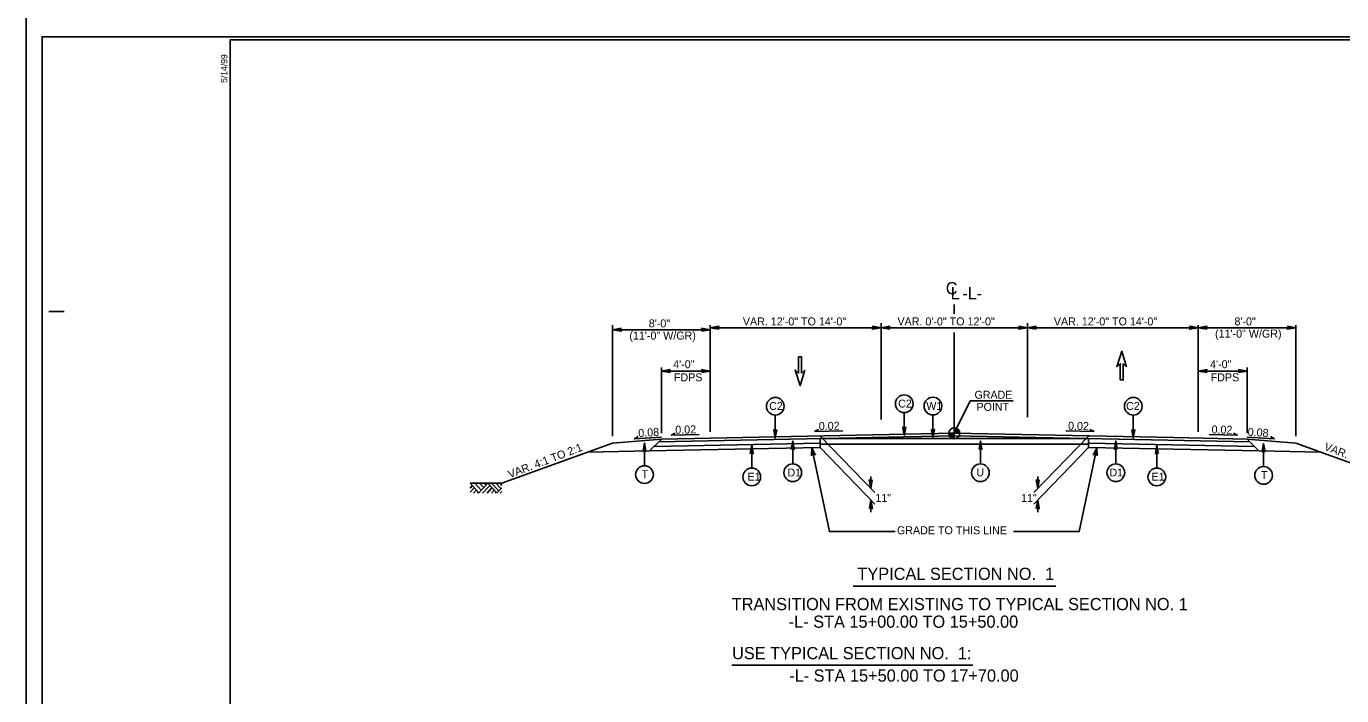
# Model space of a CAD drawing. Extents: x 1901670 to 1902225, y 193498 to 194278.
# Drawn here: x 1901965.8 to 1902073.7, y 194101.8 to 194156.6 of the extents above; entities that cross this region are included whole.
import ezdxf

# ---------------------------------------------------------------- set-up
doc = ezdxf.new("R2010")
doc.units = 0
for name, color, linetype in [('Old_Level_1', 7, 'Continuous'), ('Old_Level_11', 7, 'Continuous'), ('Old_Level_2', 7, 'Continuous'), ('Old_Level_20', 7, 'Continuous'), ('Prop Dimension', 7, 'Continuous'), ('Prop Dimension Text', 7, 'Continuous'), ('Sheet Border Standard 30in CELL', 7, 'Continuous'), ('Sheet Cutting Line CELL', 7, 'Continuous'), ('Sheet Plot Border Inside CELL', 7, 'Continuous'), ('Sheet Plot Border Outside CELL', 7, 'Continuous'), ('Typical Pavement Slope CELL', 7, 'Continuous'), ('Typical Terminator CELL', 7, 'Continuous'), ('Typical Text Grade Point CELL', 7, 'Continuous')]:
    doc.layers.add(name, color=color, linetype=linetype)

# ---------------------------------------------------------------- blocks, each defined once
blk = doc.blocks.new('TERMINATOR')
at = {"layer": 'Typical Terminator CELL'}
blk.add_lwpolyline([(-0.469, 0.081), (0, 0), (-0.471, -0.083), (-0.411, 0)], close=True, dxfattribs=at)

msp = doc.modelspace()

# ---------------------------------------------------------------- linework, layer by layer
at = {"layer": 'Old_Level_1'}
for p, q in [((1902041.9, 194133.06), (1902041.9, 194133.82)), ((1902041.9, 194123.27), (1902041.9, 194131.54)), ((1902041.9, 194123.27), (1902017.9, 194122.79)), ((1902018.69, 194123.11), (1902019.02, 194123.27)), ((1902021, 194123.16), (1902018.69, 194123.11)), ((1902030.45, 194123.41), (1902030.78, 194123.58)), ((1902032.76, 194123.46), (1902030.45, 194123.41)), ((1902041.45, 194123.27), (1902041.9, 194123.27)), ((1902041.9, 194123.27), (1902041.9, 194123.72)), ((1902042.35, 194123.27), (1902041.9, 194123.27)), ((1902041.9, 194122.82), (1902041.9, 194123.27)), ((1902041.9, 194123.27), (1902041.9, 194122.82)), ((1902041.9, 194123.27), (1902059.9, 194122.91)), ((1902051.04, 194123.46), (1902053.35, 194123.41)), ((1902053.35, 194123.41), (1902053.02, 194123.58)), ((1902062.8, 194123.16), (1902065.11, 194123.11)), ((1902065.11, 194123.11), (1902064.78, 194123.27)), ((1902017.9, 194122.79), (1902013.9, 194122.45)), ((1902015.67, 194122.82), (1902015.99, 194123)), ((1902017.91, 194122.96), (1902015.67, 194122.82)), ((1902016.93, 194121.82), (1902017.9, 194122.79)), ((1902030.9, 194122.1), (1902016.93, 194121.82)), ((1902030.9, 194122.46), (1902017.31, 194122.19)), ((1902041.9, 194123.05), (1902017.68, 194122.56)), ((1902030.9, 194123.03), (1902035.38, 194118.41)), ((1902030.9, 194122.83), (1902030.9, 194122.1)), ((1902052.9, 194122.83), (1902030.9, 194122.83)), ((1902030.9, 194122.38), (1902052.9, 194122.38)), ((1902030.9, 194122.1), (1902035.38, 194117.47)), ((1902041.9, 194123.05), (1902066.12, 194122.56)), ((1902052.9, 194123.03), (1902048.42, 194118.41)), ((1902052.9, 194122.1), (1902048.42, 194117.47)), ((1902052.9, 194122.83), (1902052.9, 194122.1)), ((1902052.9, 194122.46), (1902066.5, 194122.19)), ((1902052.9, 194122.1), (1902066.87, 194121.82)), ((1902059.9, 194122.91), (1902065.9, 194122.79)), ((1902065.9, 194122.96), (1902068.13, 194122.82)), ((1902066.87, 194121.82), (1902065.9, 194122.79)), ((1902065.9, 194122.79), (1902069.9, 194122.45)), ((1902068.13, 194122.82), (1902067.81, 194123)), ((1902016.93, 194121.82), (1902011.86, 194121.72)), ((1902066.87, 194121.82), (1902071.94, 194121.72)), ((1902002.21, 194119.17), (1902002.93, 194118.39)), ((1902002.21, 194118.77), (1902002.39, 194118.97)), ((1902002.21, 194118.43), (1902002.55, 194118.8)), ((1902002.6, 194119.18), (1902003.13, 194118.6)), ((1902002.93, 194118.39), (1902003.66, 194119.18)), ((1902003, 194119.18), (1902003.33, 194118.82)), ((1902003.24, 194118.37), (1902003.83, 194119)), ((1902003.4, 194119.18), (1902003.53, 194119.03)), ((1902003.61, 194118.37), (1902004.01, 194118.8)), ((1902003.66, 194119.18), (1902004.4, 194118.38)), ((1902003.98, 194119.18), (1902004.56, 194118.55)), ((1902004.32, 194119.18), (1902004.73, 194118.73)), ((1902004.4, 194118.38), (1902004.81, 194118.81)), ((1902004.64, 194119.18), (1902004.81, 194118.99)), ((1902035.06, 194119.74), (1902035.06, 194118.74)), ((1902048.74, 194119.74), (1902048.74, 194118.74)), ((1902002.5, 194118.37), (1902002.72, 194118.61)), ((1902002.81, 194118.37), (1902002.88, 194118.45)), ((1902003.98, 194118.37), (1902004.19, 194118.6)), ((1902004.27, 194118.37), (1902004.34, 194118.45)), ((1902004.67, 194118.37), (1902004.81, 194118.51)), ((1902035.06, 194117.8), (1902035.06, 194116.8)), ((1902048.74, 194117.8), (1902048.74, 194116.8))]:
    msp.add_line(p, q, dxfattribs=at)
for points in [[(1902041.45, 194123.27), (1902041.45, 194123.22)], [(1902041.46, 194123.27), (1902041.46, 194123.16)], [(1902041.47, 194123.27), (1902041.47, 194123.13)], [(1902041.48, 194123.27), (1902041.48, 194123.1)], [(1902041.49, 194123.27), (1902041.49, 194123.08)], [(1902041.5, 194123.27), (1902041.5, 194123.06)], [(1902041.51, 194123.27), (1902041.51, 194123.05)], [(1902041.52, 194123.27), (1902041.52, 194123.03)], [(1902041.52, 194123.27), (1902041.52, 194123.02)], [(1902041.53, 194123.27), (1902041.53, 194123)], [(1902041.54, 194123.27), (1902041.54, 194122.99)], [(1902041.55, 194123.27), (1902041.55, 194122.98)], [(1902041.56, 194123.27), (1902041.56, 194122.97)], [(1902041.57, 194123.27), (1902041.57, 194122.96)], [(1902041.58, 194123.27), (1902041.58, 194122.95)], [(1902041.59, 194123.27), (1902041.59, 194122.94)], [(1902041.6, 194123.27), (1902041.6, 194122.93)], [(1902041.61, 194123.27), (1902041.61, 194122.93)], [(1902041.61, 194123.27), (1902041.61, 194122.92)], [(1902041.62, 194123.27), (1902041.62, 194122.91)], [(1902041.63, 194123.27), (1902041.63, 194122.9)], [(1902041.64, 194123.27), (1902041.64, 194122.9)], [(1902041.65, 194123.27), (1902041.65, 194122.89)], [(1902041.66, 194123.27), (1902041.66, 194122.89)], [(1902041.67, 194123.27), (1902041.67, 194122.88)], [(1902041.68, 194123.27), (1902041.68, 194122.87)], [(1902041.69, 194123.27), (1902041.69, 194122.87)], [(1902041.7, 194123.27), (1902041.7, 194122.86)], [(1902041.7, 194123.27), (1902041.7, 194122.86)], [(1902041.71, 194123.27), (1902041.71, 194122.86)], [(1902041.72, 194123.27), (1902041.72, 194122.85)], [(1902041.73, 194123.27), (1902041.73, 194122.85)], [(1902041.74, 194123.27), (1902041.74, 194122.84)], [(1902041.75, 194123.27), (1902041.75, 194122.84)], [(1902041.76, 194123.27), (1902041.76, 194122.84)], [(1902041.77, 194123.27), (1902041.77, 194122.84)], [(1902041.78, 194123.27), (1902041.78, 194122.83)], [(1902041.79, 194123.27), (1902041.79, 194122.83)], [(1902041.79, 194123.27), (1902041.79, 194122.83)], [(1902041.8, 194123.27), (1902041.8, 194122.83)], [(1902041.81, 194123.27), (1902041.81, 194122.82)], [(1902041.82, 194123.27), (1902041.82, 194122.82)], [(1902041.83, 194123.27), (1902041.83, 194122.82)], [(1902041.84, 194123.27), (1902041.84, 194122.82)], [(1902041.85, 194123.27), (1902041.85, 194122.82)], [(1902041.86, 194123.27), (1902041.86, 194122.82)], [(1902041.87, 194123.27), (1902041.87, 194122.82)], [(1902041.88, 194123.27), (1902041.88, 194122.82)], [(1902041.88, 194123.27), (1902041.88, 194122.82)], [(1902041.89, 194123.27), (1902041.89, 194122.82), (1902041.89, 194122.82)], [(1902041.9, 194123.72), (1902041.9, 194123.72), (1902041.9, 194123.27)], [(1902041.91, 194123.72), (1902041.91, 194123.27)], [(1902041.92, 194123.71), (1902041.92, 194123.27)], [(1902041.93, 194123.71), (1902041.93, 194123.27)], [(1902041.94, 194123.71), (1902041.94, 194123.27)], [(1902041.95, 194123.71), (1902041.95, 194123.27)], [(1902041.96, 194123.71), (1902041.96, 194123.27)], [(1902041.97, 194123.71), (1902041.97, 194123.27)], [(1902041.98, 194123.71), (1902041.98, 194123.27)], [(1902041.99, 194123.71), (1902041.99, 194123.27)], [(1902041.99, 194123.71), (1902041.99, 194123.27)], [(1902042, 194123.7), (1902042, 194123.27)], [(1902042.01, 194123.7), (1902042.01, 194123.27)], [(1902042.02, 194123.7), (1902042.02, 194123.27)], [(1902042.03, 194123.7), (1902042.03, 194123.27)], [(1902042.04, 194123.69), (1902042.04, 194123.27)], [(1902042.05, 194123.69), (1902042.05, 194123.27)], [(1902042.06, 194123.69), (1902042.06, 194123.27)], [(1902042.07, 194123.68), (1902042.07, 194123.27)], [(1902042.08, 194123.68), (1902042.08, 194123.27)], [(1902042.08, 194123.68), (1902042.08, 194123.27)], [(1902042.09, 194123.67), (1902042.09, 194123.27)], [(1902042.1, 194123.67), (1902042.1, 194123.27)], [(1902042.11, 194123.66), (1902042.11, 194123.27)], [(1902042.12, 194123.66), (1902042.12, 194123.27)], [(1902042.13, 194123.65), (1902042.13, 194123.27)], [(1902042.14, 194123.65), (1902042.14, 194123.27)], [(1902042.15, 194123.64), (1902042.15, 194123.27)], [(1902042.16, 194123.64), (1902042.16, 194123.27)], [(1902042.17, 194123.63), (1902042.17, 194123.27)], [(1902042.17, 194123.62), (1902042.17, 194123.27)], [(1902042.18, 194123.62), (1902042.18, 194123.27)], [(1902042.19, 194123.61), (1902042.19, 194123.27)], [(1902042.2, 194123.6), (1902042.2, 194123.27)], [(1902042.21, 194123.59), (1902042.21, 194123.27)], [(1902042.22, 194123.58), (1902042.22, 194123.27)], [(1902042.23, 194123.57), (1902042.23, 194123.27)], [(1902042.24, 194123.56), (1902042.24, 194123.27)], [(1902042.25, 194123.55), (1902042.25, 194123.27)], [(1902042.26, 194123.54), (1902042.26, 194123.27)], [(1902042.26, 194123.53), (1902042.26, 194123.27)], [(1902042.27, 194123.52), (1902042.27, 194123.27)], [(1902042.28, 194123.5), (1902042.28, 194123.27)], [(1902042.29, 194123.49), (1902042.29, 194123.27)], [(1902042.3, 194123.47), (1902042.3, 194123.27)], [(1902042.31, 194123.45), (1902042.31, 194123.27)], [(1902042.32, 194123.43), (1902042.32, 194123.27)], [(1902042.33, 194123.41), (1902042.33, 194123.27)], [(1902042.34, 194123.38), (1902042.34, 194123.27)], [(1902042.35, 194123.33), (1902042.35, 194123.27)], [(1902030.52, 194121.48), (1902030.22, 194122.08), (1902030.19, 194121.41)], [(1902030.22, 194122.08), (1902031.66, 194115.23), (1902037.05, 194115.23)], [(1902053.58, 194122.08), (1902052.14, 194115.23), (1902046.75, 194115.23)], [(1902053.28, 194121.48), (1902053.58, 194122.08), (1902053.61, 194121.41)], [(1902002.21, 194119.18), (1902004.81, 194119.18)]]:
    msp.add_lwpolyline(points, dxfattribs=at)
msp.add_circle((1902041.9, 194123.27), 0.45, dxfattribs=at)
for start, end in [(179.9905, 269.9905), (359.9905, 89.9905)]:
    msp.add_arc((1902041.9, 194123.27), 0.45, start, end, dxfattribs=at)
at = {"layer": 'Old_Level_11'}
for p, q in [((1902027.23, 194124.76), (1902027.23, 194122.89)), ((1902037.8, 194124.96), (1902037.8, 194123.09)), ((1902040.15, 194124.77), (1902040.15, 194122.9)), ((1902056.57, 194124.76), (1902056.57, 194122.89)), ((1902016.51, 194120.6), (1902016.51, 194122.48)), ((1902025.3, 194120.42), (1902025.3, 194122.29)), ((1902028.66, 194120.76), (1902028.66, 194122.64)), ((1902044.04, 194120.76), (1902044.04, 194122.64)), ((1902055.14, 194120.76), (1902055.14, 194122.64)), ((1902058.5, 194120.42), (1902058.5, 194122.29)), ((1902067.25, 194120.55), (1902067.25, 194122.42)), ((1902033.61, 194110.75), (1902050.23, 194110.75)), ((1902023.67, 194104.25), (1902043.41, 194104.25))]:
    msp.add_line(p, q, dxfattribs=at)
for points in [[(1902027.35, 194123.56), (1902027.23, 194122.89), (1902027.12, 194123.56), (1902027.23, 194123.47)], [(1902037.92, 194123.76), (1902037.8, 194123.09), (1902037.68, 194123.76), (1902037.8, 194123.68)], [(1902040.03, 194123.57), (1902040.15, 194122.9), (1902040.27, 194123.58), (1902040.15, 194123.49)], [(1902056.45, 194123.56), (1902056.57, 194122.89), (1902056.69, 194123.56), (1902056.57, 194123.47)], [(1902016.4, 194121.81), (1902016.51, 194122.48), (1902016.63, 194121.8), (1902016.51, 194121.89)], [(1902025.18, 194121.62), (1902025.3, 194122.29), (1902025.42, 194121.61), (1902025.3, 194121.7)], [(1902028.54, 194121.97), (1902028.66, 194122.64), (1902028.78, 194121.96), (1902028.66, 194122.05)], [(1902043.93, 194121.96), (1902044.04, 194122.64), (1902044.16, 194121.96), (1902044.04, 194122.05)], [(1902055.26, 194121.97), (1902055.14, 194122.64), (1902055.02, 194121.96), (1902055.14, 194122.05)], [(1902058.62, 194121.62), (1902058.5, 194122.29), (1902058.38, 194121.61), (1902058.5, 194121.7)], [(1902067.37, 194121.75), (1902067.25, 194122.42), (1902067.13, 194121.75), (1902067.25, 194121.83)]]:
    msp.add_lwpolyline(points, close=True, dxfattribs=at)
for centre in [(1902037.8, 194125.69), (1902027.23, 194125.48), (1902040.15, 194125.5), (1902056.57, 194125.48), (1902016.51, 194119.88), (1902025.3, 194119.69), (1902028.66, 194120.04), (1902044.04, 194120.04), (1902055.14, 194120.04), (1902058.5, 194119.69), (1902067.25, 194119.82)]:
    msp.add_circle(centre, 0.725, dxfattribs=at)
at = {"layer": 'Prop Dimension'}
for p, q in [((1902021.9, 194124.43), (1902021.9, 194132.13)), ((1902021.9, 194131.92), (1902035.9, 194131.92)), ((1902035.9, 194124.4), (1902035.9, 194132.29)), ((1902035.9, 194131.92), (1902047.9, 194131.92)), ((1902047.9, 194124.59), (1902047.9, 194132.29)), ((1902047.9, 194131.92), (1902061.9, 194131.92)), ((1902061.9, 194124.43), (1902061.9, 194132.13))]:
    msp.add_line(p, q, dxfattribs=at)
for points in [[(1902056.02, 194128.72), (1902055.75, 194128.97), (1902055.75, 194127.64), (1902055.5, 194127.64), (1902055.5, 194128.97), (1902055.23, 194128.72), (1902055.63, 194130)], [(1902056.02, 194128.72), (1902055.75, 194128.97), (1902055.75, 194127.64), (1902055.5, 194127.64), (1902055.5, 194128.97), (1902055.23, 194128.72), (1902055.63, 194130)], [(1902029.66, 194128.45), (1902029.39, 194128.2), (1902029.39, 194129.53), (1902029.14, 194129.53), (1902029.14, 194128.2), (1902028.87, 194128.45), (1902029.27, 194127.18)], [(1902029.66, 194128.45), (1902029.39, 194128.2), (1902029.39, 194129.53), (1902029.14, 194129.53), (1902029.14, 194128.2), (1902028.87, 194128.45), (1902029.27, 194127.18)]]:
    msp.add_lwpolyline(points, close=True, dxfattribs=at)
at = {"layer": 'Prop Dimension Text'}
for p, q in [((1902013.9, 194123.27), (1902013.9, 194132.13)), ((1902013.9, 194123.03), (1902013.9, 194132.13)), ((1902013.9, 194131.76), (1902021.9, 194131.76)), ((1902021.9, 194123.38), (1902021.9, 194132.13)), ((1902061.9, 194123.38), (1902061.9, 194132.13)), ((1902069.9, 194131.92), (1902061.9, 194131.92)), ((1902069.9, 194123.27), (1902069.9, 194132.13)), ((1902069.9, 194123.03), (1902069.9, 194132.13)), ((1902017.9, 194123.29), (1902017.9, 194128.65)), ((1902065.9, 194123.29), (1902065.9, 194128.65)), ((1902021.9, 194128.37), (1902017.9, 194128.37)), ((1902061.9, 194128.37), (1902065.9, 194128.37))]:
    msp.add_line(p, q, dxfattribs=at)
at = {"layer": 'Sheet Border Standard 30in CELL'}
for p, q in [((1901982.64, 194155.51), (1901982.64, 194155.51)), ((1901967.69, 194133.26), (1901968.94, 194133.26))]:
    msp.add_line(p, q, dxfattribs=at)
msp.add_lwpolyline([(1902132.54, 194155.51), (1901982.54, 194155.51), (1901982.54, 194050.51), (1902132.54, 194050.51)], close=True, dxfattribs=at)
at = {"layer": 'Sheet Cutting Line CELL'}
msp.add_line((1901965.84, 194158.01), (1901965.84, 194048.01), dxfattribs=at)
at = {"layer": 'Sheet Plot Border Inside CELL'}
msp.add_lwpolyline([(1902133.79, 194155.77), (1901967.14, 194155.77), (1901967.14, 194050.26), (1902133.79, 194050.26)], close=True, dxfattribs=at)
at = {"layer": 'Sheet Plot Border Outside CELL'}
msp.add_lwpolyline([(1902134.24, 194158.01), (1901965.84, 194158.01), (1901965.84, 194048.01), (1902134.24, 194048.01)], close=True, dxfattribs=at)
at = {"layer": 'Typical Pavement Slope CELL'}
for p, q in [((1902004.81, 194119.18), (1902013.9, 194122.45)), ((1902078.99, 194119.18), (1902069.9, 194122.45))]:
    msp.add_line(p, q, dxfattribs=at)
at = {"layer": 'Typical Text Grade Point CELL'}
for p, q in [((1902041.9, 194123.27), (1902043.2, 194125.94)), ((1902043.2, 194125.94), (1902046.73, 194125.94))]:
    msp.add_line(p, q, dxfattribs=at)

# ---------------------------------------------------------------- block references
at = {"layer": 'Old_Level_1', "xscale": 1.5, "yscale": 1.5}
for p, rotation in [((1902035.06, 194118.74), -90), ((1902048.74, 194118.74), -90), ((1902035.06, 194117.8), 90), ((1902048.74, 194117.8), 90)]:
    msp.add_blockref('TERMINATOR', p, dxfattribs=dict(at, rotation=rotation))
at = {"layer": 'Prop Dimension', "xscale": 1.5, "rotation": 180}
for p, yscale in [((1902013.9, 194131.76), -1.5), ((1902021.9, 194131.92), 1.5), ((1902035.9, 194131.92), 1.5), ((1902047.9, 194131.92), 1.5), ((1902061.9, 194131.92), 1.5), ((1902061.9, 194128.37), 1.5), ((1902017.9, 194128.37), -1.5)]:
    msp.add_blockref('TERMINATOR', p, dxfattribs=dict(at, yscale=yscale))
at = {"layer": 'Prop Dimension', "xscale": 1.5}
for p, yscale in [((1902021.9, 194131.76), -1.5), ((1902035.9, 194131.92), 1.5), ((1902047.9, 194131.92), 1.5), ((1902061.9, 194131.92), 1.5), ((1902061.9, 194131.92), -1.5), ((1902069.9, 194131.92), 1.5), ((1902021.9, 194128.37), -1.5), ((1902065.9, 194128.37), 1.5)]:
    msp.add_blockref('TERMINATOR', p, dxfattribs=dict(at, yscale=yscale))

# ---------------------------------------------------------------- texts
at = {"layer": 'Old_Level_1'}
for rotation, p in [(20.8342, (1902005.47, 194119.57)), (339.1658, (1902072.15, 194121.92))]:
    msp.add_text('VAR. 4:1 TO 2:1', height=0.656, rotation=rotation, dxfattribs=at).set_placement(p)
for s, height, p in [('11"', 0.649, (1902035.44, 194117.65)), ('11"', 0.649, (1902047.38, 194117.65)), ('GRADE TO THIS LINE', 0.656, (1902037.2, 194114.99))]:
    msp.add_text(s, height=height, dxfattribs=at).set_placement(p)
at = {"layer": 'Old_Level_11'}
for s, p in [('TYPICAL SECTION NO.  1', (1902033.96, 194111.25)), ('TRANSITION FROM EXISTING TO TYPICAL SECTION NO. 1', (1902023.66, 194108.77)), ('-L- STA 15+00.00 TO 15+50.00', (1902028.33, 194107.33)), ('USE TYPICAL SECTION NO.  1:', (1902023.69, 194104.75)), ('-L- STA 15+50.00 TO 17+70.00', (1902028.37, 194102.91))]:
    msp.add_text(s, height=1, dxfattribs=at).set_placement(p)
at = {"layer": 'Old_Level_2'}
msp.add_text('C', height=1, dxfattribs=at).set_placement((1902041.2, 194134.66))
for s, height, rotation, p in [('L', 1, 359.9469, (1902041.6, 194134.26)), ('-L-', 1, 359.9469, (1902042.55, 194134.25)), ('0.02', 0.656, 1.1916, (1902030.8, 194123.53)), ('0.02', 0.656, 358.8084, (1902051.22, 194123.56)), ('0.08', 0.656, 3.7166, (1902016.02, 194122.95)), ('0.02', 0.656, 1.1916, (1902019.04, 194123.23)), ('0.02', 0.656, 358.8084, (1902062.98, 194123.26)), ('0.08', 0.656, 356.2834, (1902065.93, 194123.07))]:
    msp.add_text(s, height=height, rotation=rotation, dxfattribs=at).set_placement(p)
at = {"layer": 'Old_Level_20'}
for s, p in [('C2', (1902026.73, 194125.18)), ('C2', (1902037.3, 194125.38)), ('W1', (1902039.61, 194125.19)), ('C2', (1902055.98, 194125.18)), ('T', (1902016.28, 194119.59)), ('E1', (1902024.96, 194119.39)), ('D1', (1902028.23, 194119.73)), ('U', (1902043.71, 194119.74)), ('D1', (1902054.62, 194119.73)), ('E1', (1902058.07, 194119.39)), ('T', (1902067.04, 194119.53))]:
    msp.add_text(s, height=0.649, dxfattribs=at).set_placement(p)
at = {"layer": 'Prop Dimension'}
for s, p in [('VAR. 12\'-0" TO 14\'-0" ', (1902024.57, 194132.11)), ('VAR. 0\'-0" TO 12\'-0" ', (1902037.24, 194132.11)), ('VAR. 12\'-0" TO 14\'-0" ', (1902050.06, 194132.11))]:
    msp.add_text(s, height=0.656, dxfattribs=at).set_placement(p)
at = {"layer": 'Prop Dimension Text'}
for s, p in [('8\'-0"', (1902016.86, 194131.95)), ('(11\'-0" W/GR)', (1902063.27, 194131.11)), ('8\'-0"', (1902064.86, 194132.11)), ('(11\'-0" W/GR)', (1902015.27, 194130.95)), ('4\'-0"', (1902018.86, 194128.6)), ('4\'-0"', (1902062.86, 194128.6)), ('FDPS', (1902018.92, 194127.53)), ('FDPS', (1902062.91, 194127.53))]:
    msp.add_text(s, height=0.656, dxfattribs=at).set_placement(p)
at = {"layer": 'Sheet Border Standard 30in CELL'}
msp.add_text('5/14/99', height=0.525, rotation=90, dxfattribs=at).set_placement((1901982.32, 194151.99))
at = {"layer": 'Typical Text Grade Point CELL'}
for s, p in [('GRADE', (1902043.56, 194126.1)), ('POINT', (1902043.72, 194125.11))]:
    msp.add_text(s, height=0.652, dxfattribs=at).set_placement(p)

doc.saveas('drawing.dxf')
